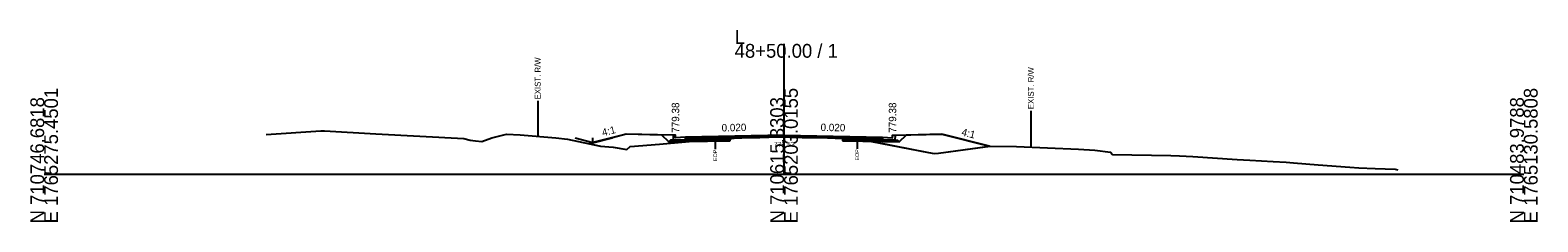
# Model space of a CAD drawing. Extents: x -26 to 5303, y -10 to 9578.
# Drawn here: x 2997.2 to 3302.8, y 8490.3 to 8529.2 of the extents above; entities that cross this region are included whole.
import ezdxf

# ---------------------------------------------------------------- set-up
doc = ezdxf.new("R2010")
doc.units = 0
for name, color, linetype in [('Default', 7, 'Continuous'), ('Exist CMT Pavement', 7, 'Continuous'), ('Exist Cross Section Cell', 7, 'Continuous'), ('Exist XS Ground Line', 7, 'Continuous'), ('Old_Level_10', 7, 'Continuous'), ('Old_Level_3', 7, 'Continuous'), ('Prop CMT Conc Surface', 7, 'Continuous'), ('Prop CMT Concrete Structures', 7, 'Continuous'), ('Prop CMT Pvmt Course 1', 7, 'Continuous'), ('Prop CMT Pvmt Course 1 CG', 7, 'Continuous'), ('Prop CMT Pvmt Course 2', 7, 'Continuous'), ('Prop CMT Pvmt Course 3', 7, 'Continuous'), ('Prop CMT Pvmt Surface', 7, 'Continuous'), ('Prop CMT Slope Grass', 7, 'Continuous'), ('Prop CMT Subgrade Earthwork', 7, 'Continuous'), ('Prop XS Earthwork Shape', 7, 'Continuous'), ('Prop XS Hydro Elevations', 7, 'Continuous'), ('Prop XS SE Text', 7, 'Continuous'), ('Prop XS Side Slope Text', 7, 'Continuous'), ('Prop XS Wedging', 7, 'Continuous'), ('Scratch_Level_2', 7, 'Continuous')]:
    doc.layers.add(name, color=color, linetype=linetype)

msp = doc.modelspace()

# ---------------------------------------------------------------- linework, layer by layer
at = {"layer": 'Exist CMT Pavement'}
msp.add_lwpolyline([(3139.03, 8507.23), (3139.9, 8507.29), (3140.38, 8507.32), (3141.42, 8507.35), (3143.3, 8507.39), (3146.09, 8507.47), (3146.94, 8507.49), (3148.48, 8507.53), (3148.95, 8507.54), (3151.15, 8507.51), (3152.03, 8507.5), (3152.46, 8507.48), (3153.66, 8507.45), (3154.3, 8507.44), (3154.66, 8507.43), (3155.89, 8507.41), (3157.51, 8507.39), (3158.83, 8507.35), (3159.82, 8507.33), (3160.37, 8507.31), (3161.91, 8507.28)], dxfattribs=at)
at = {"layer": 'Exist Cross Section Cell'}
for p, q in [((3150, 8500), (3150, 8526.4)), ((3000, 8500), (3150, 8500)), ((3150, 8500), (3300, 8500))]:
    msp.add_line(p, q, dxfattribs=at)
at = {"layer": 'Exist XS Ground Line'}
msp.add_lwpolyline([(3045, 8508.02), (3056.1, 8508.8), (3056.82, 8508.75), (3067.24, 8508.17), (3085.07, 8507.19), (3086.36, 8506.87), (3087.45, 8506.72), (3088.71, 8506.61), (3090.73, 8507.35), (3093.73, 8508.08), (3096.48, 8507.98), (3103.72, 8507.34), (3106.1, 8507.06), (3112.8, 8505.68), (3115.33, 8505.43), (3118.11, 8504.99), (3118.78, 8505.61), (3124.75, 8506.06), (3136.03, 8507.1), (3136.7, 8507.13), (3137.69, 8507.18), (3139.03, 8507.23), (3139.4, 8507.25), (3139.9, 8507.29), (3140.38, 8507.32), (3143.3, 8507.39), (3145.1, 8507.43), (3146.09, 8507.47), (3148.48, 8507.53), (3148.95, 8507.54), (3151.15, 8507.51), (3152.03, 8507.5), (3152.46, 8507.48), (3153.66, 8507.45), (3154.66, 8507.43), (3156.14, 8507.4), (3157.51, 8507.39), (3158.83, 8507.35), (3159.82, 8507.33), (3160.37, 8507.31), (3161.45, 8507.29), (3161.91, 8507.28), (3162.92, 8507.24), (3163.5, 8507.24), (3164.47, 8507.19), (3164.83, 8507.19), (3179.32, 8504.38), (3180.43, 8504.17), (3181.32, 8504.26), (3191.77, 8505.66), (3197.17, 8505.59), (3209.72, 8505.05), (3213.03, 8504.82), (3216.21, 8504.45), (3216.62, 8503.95), (3228.44, 8503.77), (3230.19, 8503.71), (3232.86, 8503.56), (3241.85, 8502.97), (3244.45, 8502.79), (3249.16, 8502.54), (3251.81, 8502.41), (3253.27, 8502.31), (3258.33, 8501.9), (3264.69, 8501.4), (3266.53, 8501.29), (3269.87, 8501.14), (3273.89, 8500.97), (3274.43, 8500.89)], dxfattribs=at)
at = {"layer": 'Old_Level_10'}
for p, q in [((3100.06, 8514.86), (3100.06, 8507.46)), ((3200.06, 8512.86), (3200.06, 8505.46)), ((3164.83, 8507.19), (3164.83, 8505.14)), ((3136.03, 8507.1), (3136.03, 8505.05))]:
    msp.add_line(p, q, dxfattribs=at)
at = {"layer": 'Prop CMT Conc Surface'}
for points in [[(3128, 8507.38), (3128, 8507.88), (3127.5, 8507.88)], [(3130, 8507.5), (3128, 8507.38)], [(3170, 8507.5), (3172, 8507.38)], [(3172, 8507.38), (3172.01, 8507.88), (3172.51, 8507.88)]]:
    msp.add_lwpolyline(points, dxfattribs=at)
at = {"layer": 'Prop CMT Concrete Structures'}
for points in [[(3130, 8507.5), (3128, 8507.38), (3128, 8507.88), (3127.5, 8507.88)], [(3127.5, 8507.88), (3127.5, 8506.86), (3130, 8506.91)], [(3130, 8506.91), (3130, 8507.5)], [(3170, 8507.5), (3172, 8507.38), (3172.01, 8507.88), (3172.51, 8507.88)], [(3172.51, 8507.88), (3172.5, 8506.86), (3170, 8506.91)], [(3170, 8506.91), (3170, 8507.5)]]:
    msp.add_lwpolyline(points, dxfattribs=at)
at = {"layer": 'Prop CMT Pvmt Course 1'}
for points in [[(3150, 8507.9), (3130, 8507.5)], [(3130, 8507.5), (3130, 8507.25)], [(3130, 8507.25), (3139.03, 8507.43)], [(3139.03, 8507.43), (3150, 8507.65)], [(3139.03, 8507.43), (3139.03, 8507.43)], [(3150, 8507.65), (3150, 8507.9)], [(3150, 8507.9), (3170, 8507.5)], [(3150, 8507.65), (3150, 8507.65), (3150, 8507.65)], [(3161.91, 8507.41), (3150, 8507.65)], [(3170, 8507.25), (3161.91, 8507.41)], [(3161.91, 8507.41), (3161.91, 8507.41)], [(3170, 8507.5), (3170, 8507.25)]]:
    msp.add_lwpolyline(points, dxfattribs=at)
at = {"layer": 'Prop CMT Pvmt Course 1 CG'}
for points in [[(3130, 8506.91), (3127, 8506.85), (3126.66, 8506.51)], [(3126.66, 8506.51), (3130, 8506.58)], [(3130, 8506.58), (3130, 8506.91)], [(3170, 8506.91), (3173, 8506.85), (3173.34, 8506.51)], [(3170, 8506.58), (3170, 8506.91)], [(3173.34, 8506.51), (3170, 8506.58)]]:
    msp.add_lwpolyline(points, dxfattribs=at)
at = {"layer": 'Prop CMT Pvmt Course 2'}
for points in [[(3139.03, 8507.43), (3130, 8507.25)], [(3130, 8507.25), (3130, 8506.91)], [(3139.03, 8507.09), (3139.03, 8507.43)], [(3161.91, 8507.08), (3161.91, 8507.41)], [(3161.91, 8507.41), (3170, 8507.25)], [(3170, 8507.25), (3170, 8506.91)], [(3130, 8506.91), (3139.03, 8507.09)], [(3170, 8506.91), (3161.91, 8507.08)]]:
    msp.add_lwpolyline(points, dxfattribs=at)
at = {"layer": 'Prop CMT Pvmt Course 3'}
for points in [[(3139.03, 8507.09), (3130, 8506.91)], [(3130, 8506.91), (3130, 8506.58)], [(3130, 8506.58), (3139.03, 8506.76)], [(3139.03, 8506.76), (3139.03, 8507.09)], [(3161.91, 8507.08), (3170, 8506.91)], [(3161.91, 8506.74), (3161.91, 8507.08)], [(3170, 8506.58), (3161.91, 8506.74)], [(3170, 8506.91), (3170, 8506.58)]]:
    msp.add_lwpolyline(points, dxfattribs=at)
at = {"layer": 'Prop CMT Pvmt Surface'}
for points in [[(3150, 8507.9), (3130, 8507.5)], [(3150, 8507.9), (3170, 8507.5)]]:
    msp.add_lwpolyline(points, dxfattribs=at)
at = {"layer": 'Prop CMT Slope Grass'}
for points in [[(3127.5, 8507.88), (3118, 8508.07), (3110.41, 8506.17)], [(3172.51, 8507.88), (3182.01, 8508.07), (3191.68, 8505.65)]]:
    msp.add_lwpolyline(points, dxfattribs=at)
at = {"layer": 'Prop CMT Subgrade Earthwork'}
for p, q in [((3139.03, 8506.76), (3139.03, 8507.23)), ((3161.91, 8506.74), (3161.91, 8507.28))]:
    msp.add_line(p, q, dxfattribs=at)
for points in [[(3130, 8506.58), (3126.66, 8506.51), (3125.25, 8507.92)], [(3170, 8506.58), (3173.34, 8506.51), (3174.75, 8507.92)], [(3139.03, 8506.76), (3130, 8506.58)], [(3161.91, 8506.74), (3170, 8506.58)]]:
    msp.add_lwpolyline(points, dxfattribs=at)
at = {"layer": 'Prop XS Earthwork Shape'}
for p, q in [((3115.22, 8507.37), (3111.22, 8506.37)), ((3115.22, 8507.37), (3111.22, 8506.37)), ((3126.66, 8506.51), (3125.25, 8507.92)), ((3111.22, 8506.37), (3110.41, 8506.17)), ((3111.22, 8506.37), (3110.41, 8506.17)), ((3110.41, 8506.17), (3112.8, 8505.68)), ((3110.41, 8506.17), (3112.8, 8505.68)), ((3124.75, 8506.06), (3130.55, 8506.59)), ((3130, 8506.58), (3126.66, 8506.51)), ((3130.55, 8506.59), (3130, 8506.58)), ((3130.55, 8506.59), (3130, 8506.58))]:
    msp.add_line(p, q, dxfattribs=at)
for points in [[(3125.25, 8507.92), (3118, 8508.07), (3115.22, 8507.37)], [(3125.25, 8507.92), (3118, 8508.07), (3115.22, 8507.37)], [(3130, 8506.58), (3126.66, 8506.51), (3125.25, 8507.92)], [(3112.8, 8505.68), (3115.33, 8505.43), (3118.11, 8504.99), (3118.78, 8505.61), (3124.75, 8506.06), (3130.55, 8506.59)], [(3112.8, 8505.68), (3115.33, 8505.43), (3118.11, 8504.99)], [(3118.11, 8504.99), (3118.78, 8505.61), (3124.75, 8506.06)], [(3130.55, 8506.59), (3130.55, 8506.59)]]:
    msp.add_lwpolyline(points, dxfattribs=at)
for points in [[(3136.7, 8507.13), (3137.74, 8507.19), (3138.12, 8507.2), (3139.03, 8507.23), (3139.03, 8506.76), (3130.55, 8506.59), (3136.03, 8507.1)], [(3136.03, 8507.1), (3136.7, 8507.13), (3137.74, 8507.19), (3138.12, 8507.2), (3139.03, 8507.23), (3139.03, 8506.76), (3130.55, 8506.59)], [(3164.47, 8507.19), (3164.83, 8507.19), (3167.73, 8506.63), (3161.91, 8506.74), (3161.91, 8507.28), (3162.92, 8507.24), (3163.5, 8507.24)], [(3163.5, 8507.24), (3164.47, 8507.19), (3164.83, 8507.19), (3167.73, 8506.63), (3161.91, 8506.74), (3161.91, 8507.28), (3162.92, 8507.24)], [(3180.43, 8504.17), (3181.32, 8504.26), (3191.68, 8505.65), (3182.01, 8508.07), (3174.75, 8507.92), (3173.34, 8506.51), (3170, 8506.58), (3167.73, 8506.63), (3179.32, 8504.38)], [(3167.73, 8506.63), (3179.32, 8504.38), (3180.43, 8504.17), (3181.32, 8504.26), (3191.68, 8505.65), (3182.01, 8508.07), (3174.75, 8507.92), (3173.34, 8506.51), (3170, 8506.58)]]:
    msp.add_lwpolyline(points, close=True, dxfattribs=at)
at = {"layer": 'Prop XS Wedging'}
msp.add_lwpolyline([(3139.03, 8507.23), (3139.03, 8507.43), (3139.9, 8507.45), (3140.39, 8507.46), (3141.42, 8507.48), (3143.3, 8507.51), (3146.1, 8507.57), (3146.94, 8507.59), (3148.48, 8507.62), (3148.95, 8507.63), (3150, 8507.65), (3151.15, 8507.63), (3152.03, 8507.61), (3152.46, 8507.6), (3153.66, 8507.57), (3154.3, 8507.56), (3154.66, 8507.55), (3155.89, 8507.53), (3157.51, 8507.5), (3158.83, 8507.47), (3159.82, 8507.45), (3160.37, 8507.44), (3161.45, 8507.42), (3161.91, 8507.41), (3161.91, 8507.28), (3161.45, 8507.29), (3160.37, 8507.31), (3159.82, 8507.33), (3158.83, 8507.35), (3157.51, 8507.39), (3155.89, 8507.41), (3154.66, 8507.43), (3154.3, 8507.44), (3153.66, 8507.45), (3152.46, 8507.48), (3152.03, 8507.5), (3151.15, 8507.51), (3150, 8507.52), (3148.95, 8507.54), (3148.48, 8507.53), (3146.94, 8507.49), (3146.1, 8507.47), (3143.3, 8507.39), (3141.42, 8507.35), (3140.39, 8507.32), (3139.9, 8507.29)], close=True, dxfattribs=at)
at = {"layer": 'Scratch_Level_2'}
for q in [(3107.65, 8507.28), (3111.22, 8507.37), (3115.22, 8507.37)]:
    msp.add_line((3111.22, 8506.37), q, dxfattribs=at)

# ---------------------------------------------------------------- texts
at = {"layer": 'Default'}
msp.add_text('-', height=0.0001, dxfattribs=at).set_placement((3000, 8500))
at = {"layer": 'Exist Cross Section Cell'}
for s, p in [('L', (3140, 8526.4)), ('48+50.00 / 1', (3140, 8523.6))]:
    msp.add_text(s, height=2.8, dxfattribs=at).set_placement(p)
for s, p in [('E 1765275.4501', (3002.8, 8490)), ('E 1765203.0155', (3152.8, 8490)), ('E 1765130.5808', (3302.8, 8490)), ('N 710746.6818', (3000, 8490)), ('N 710615.3303', (3150, 8490)), ('N 710483.9788', (3300, 8490))]:
    msp.add_text(s, height=2.8, rotation=90, dxfattribs=at).set_placement(p)
at = {"layer": 'Old_Level_10'}
for s, height, p in [('EXIST. R/W', 1.181, (3100.65, 8515.16)), ('EXIST. R/W', 1.181, (3200.65, 8513.17)), ('EOP', 0.787, (3136.43, 8502.65)), ('EOP', 0.787, (3165.22, 8502.74))]:
    msp.add_text(s, height=height, rotation=90, dxfattribs=at).set_placement(p)
at = {"layer": 'Old_Level_3'}
msp.add_text('779.53', height=1, dxfattribs=at).set_placement((3147.95, 8505.53))
at = {"layer": 'Prop XS Hydro Elevations'}
for p in [(3128.75, 8508.38), (3172.75, 8508.38)]:
    msp.add_text('779.38', height=1.5, rotation=90, dxfattribs=at).set_placement(p)
at = {"layer": 'Prop XS SE Text'}
for rotation, p in [(1.1458, (3137.36, 8508.64)), (358.8542, (3157.4, 8508.75))]:
    msp.add_text('0.020', height=1.5, rotation=rotation, dxfattribs=at).set_placement(p)
at = {"layer": 'Prop XS Side Slope Text'}
for rotation, p in [(14.0362, (3113.28, 8507.66)), (345.9638, (3185.87, 8507.87))]:
    msp.add_text('4:1', height=1.5, rotation=rotation, dxfattribs=at).set_placement(p)

doc.saveas('drawing.dxf')
